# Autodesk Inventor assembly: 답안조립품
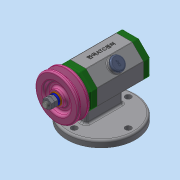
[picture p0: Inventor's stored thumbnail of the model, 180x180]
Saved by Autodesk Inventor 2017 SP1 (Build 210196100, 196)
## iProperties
Part Number: 답안조립품
Material: 일반
Document SubType Name: Assembly
Designer: 00-00
Author: 00-00
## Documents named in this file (14)
- C:\Users\00-00\Desktop\710204V1022\답안조립품.iam
- C:\Users\00-00\Desktop\710204V1022\본체.ipt
- C:\Users\00-00\Desktop\710204V1022\V벨트풀리.ipt
- C:\Users\00-00\Desktop\710204V1022\고무캡.ipt
- C:\Users\00-00\Desktop\710204V1022\너트 M8.ipt
- C:\Users\00-00\Desktop\710204V1022\뒤커버.ipt
- C:\Users\00-00\Desktop\710204V1022\베어링 15 x 32 x 9.ipt
- C:\Users\00-00\Desktop\710204V1022\볼트 M4 x 12.ipt
- C:\Users\00-00\Desktop\710204V1022\스프링와셔 8.ipt
- C:\Users\00-00\Desktop\710204V1022\앞커버.ipt
- C:\Users\00-00\Desktop\710204V1022\오일 실 15 25 7.ipt
- C:\Users\00-00\Desktop\710204V1022\와셔 8x17.ipt
- C:\Users\00-00\Desktop\710204V1022\축.ipt
- C:\Users\00-00\Desktop\710204V1022\키 3 x 3 x 12.ipt
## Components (2 placed, 2 different names)
1. V벨트풀리:1 — 각도:1
2. 고무캡:1
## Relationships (1: Angle 1)
- 각도:1 [Angle]: V벨트풀리:1
